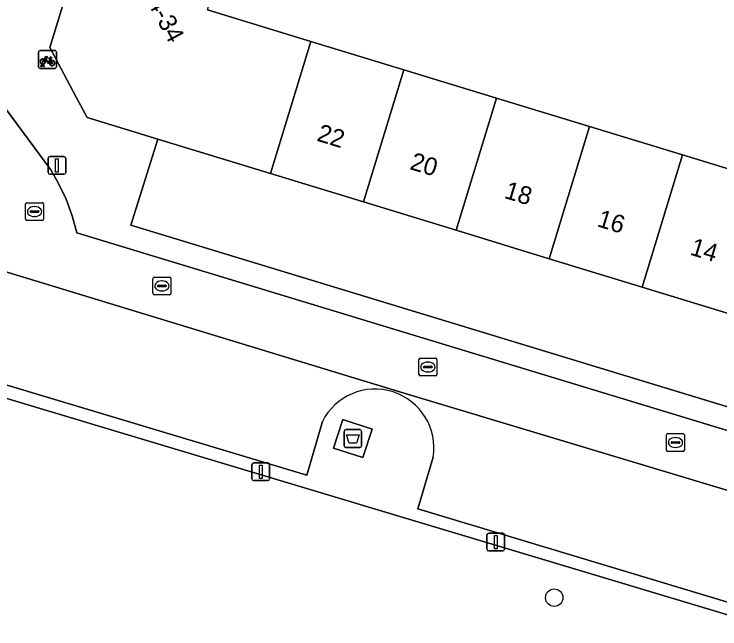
# Model space of a CAD drawing. Extents: x 160304 to 160955, y 383684 to 384161.
# Drawn here: x 160708.64 to 160748.29, y 383760.89 to 383795.43 of the extents above; entities that cross this region are included whole.
import ezdxf

# ---------------------------------------------------------------- set-up
doc = ezdxf.new("R2010")
doc.units = 0
for name, color, linetype in [('IMGEO_Afval_apart_plaats', 7, 'Continuous'), ('IMGEO_Boom', 7, 'Continuous'), ('IMGEO_Brandkraan', 7, 'Continuous'), ('IMGEO_Erf', 7, 'Continuous'), ('IMGEO_Fietsenrek', 7, 'Continuous'), ('IMGEO_Groenvoorziening', 7, 'Continuous'), ('IMGEO_Kolk', 7, 'Continuous'), ('IMGEO_Lichtmast', 7, 'Continuous'), ('IMGEO_Pand', 7, 'Continuous'), ('IMGEO_Pand_nummerreeks', 7, 'Continuous'), ('IMGEO_Parkeervlak_open', 7, 'Continuous'), ('IMGEO_Rijbaan_lokaal_open', 7, 'Continuous'), ('IMGEO_Voetpad_gesloten', 7, 'Continuous'), ('IMGEO_Voetpad_open', 7, 'Continuous')]:
    doc.layers.add(name, color=color, linetype=linetype)

msp = doc.modelspace()

# ---------------------------------------------------------------- linework, layer by layer
at = {"layer": 'IMGEO_Afval_apart_plaats'}
for p, q in [((160727.174, 383771.185), (160727.174, 383771.985)), ((160727.174, 383771.985), (160727.174, 383771.185)), ((160727.274, 383772.085), (160728.064, 383772.085)), ((160728.064, 383772.085), (160727.274, 383772.085)), ((160728.164, 383771.985), (160728.164, 383771.185)), ((160728.164, 383771.185), (160728.164, 383771.985)), ((160728.064, 383771.085), (160727.274, 383771.085)), ((160727.274, 383771.085), (160728.064, 383771.085))]:
    msp.add_line(p, q, dxfattribs=at)
msp.add_lwpolyline([(160727.317, 383771.799), (160728.021, 383771.799), (160727.872, 383771.329), (160727.466, 383771.329), (160727.317, 383771.799)], dxfattribs=at)
for centre, start, end in [((160727.274, 383771.985), 90, 180), ((160727.274, 383771.985), 90, 180), ((160728.064, 383771.985), 0, 90), ((160728.064, 383771.985), 360, 90), ((160727.274, 383771.185), 180, 270), ((160727.274, 383771.185), 180, 270), ((160728.064, 383771.185), 270, 0), ((160728.064, 383771.185), 270, 0)]:
    msp.add_arc(centre, 0.1, start, end, dxfattribs=at)
at = {"layer": 'IMGEO_Boom'}
msp.add_circle((160738.982, 383762.645), 0.489, dxfattribs=at)
at = {"layer": 'IMGEO_Brandkraan'}
for p, q in [((160709.289, 383783.912), (160709.289, 383784.764)), ((160709.364, 383784.838), (160710.216, 383784.838)), ((160709.777, 383784.618), (160709.802, 383784.618)), ((160710.29, 383784.764), (160710.29, 383783.912)), ((160709.548, 383784.332), (160709.548, 383784.344)), ((160709.986, 383784.295), (160709.588, 383784.295)), ((160709.591, 383784.381), (160709.989, 383784.381)), ((160710.032, 383784.344), (160710.032, 383784.332)), ((160710.216, 383783.838), (160709.364, 383783.838)), ((160709.8, 383784.058), (160709.775, 383784.058))]:
    msp.add_line(p, q, dxfattribs=at)
for points in [[(160709.289, 383783.912), (160709.289, 383784.764)], [(160709.364, 383784.838), (160710.216, 383784.838)], [(160710.29, 383784.764), (160710.29, 383783.912)], [(160710.216, 383783.838), (160709.364, 383783.838)]]:
    msp.add_lwpolyline(points, dxfattribs=at)
for centre, radius, start, end in [((160709.366, 383784.762), 0.0765, 91.552, 178.448), ((160709.366, 383784.762), 0.0765, 91.552, 178.448), ((160710.214, 383784.762), 0.0765, 1.552, 88.448), ((160710.214, 383784.762), 0.0765, 1.552, 88.448), ((160709.588, 383784.341), 0.0403, 85.8775, 175.7526), ((160709.585, 383784.331), 0.0366, 178.938, 274.7102), ((160709.989, 383784.338), 0.043, 264.8664, 352.4533), ((160709.993, 383784.343), 0.0386, 1.7309, 96.639), ((160709.366, 383783.914), 0.0765, 181.552, 268.448), ((160709.366, 383783.914), 0.0765, 181.552, 268.448), ((160710.214, 383783.914), 0.0765, 271.552, 358.448), ((160710.214, 383783.914), 0.0765, 271.552, 358.448)]:
    msp.add_arc(centre, radius, start, end, dxfattribs=at)
for centre, major_axis, ratio, start_param, end_param in [((160709.776, 383784.338), (-0.387, 0.002), 0.722429, 4.712389, 7.853982), ((160709.801, 383784.338), (-0.39, 0.002), 0.717154, 1.570796, 4.712389)]:
    msp.add_ellipse(centre, major_axis=major_axis, ratio=ratio, start_param=start_param, end_param=end_param, dxfattribs=at)
at = {"layer": 'IMGEO_Erf'}
msp.add_lwpolyline([(160719.497, 383795.67), (160725.313, 383793.894), (160730.532, 383792.301), (160735.749, 383790.708), (160740.967, 383789.115), (160746.185, 383787.522), (160751.401, 383785.93), (160757.279, 383784.135), (160758.769, 383789.013), (160760.453, 383794.532), (160763.405, 383804.2)], dxfattribs=at)
msp.add_lwpolyline([(160715.206, 383783.583), (160754.942, 383771.483), (160756.398, 383776.288), (160749.136, 383778.505), (160743.919, 383780.098), (160738.701, 383781.692), (160733.483, 383783.285), (160728.266, 383784.878), (160723.048, 383786.471), (160716.717, 383788.404)], close=True, dxfattribs=at)
at = {"layer": 'IMGEO_Fietsenrek'}
for p, q in [((160710.015, 383792.458), (160710.015, 383793.299)), ((160710.015, 383793.299), (160710.015, 383792.458)), ((160710.09, 383793.383), (160710.931, 383793.383)), ((160710.931, 383793.383), (160710.09, 383793.383)), ((160711.015, 383793.308), (160711.015, 383792.467)), ((160711.015, 383792.467), (160711.015, 383793.308)), ((160710.702, 383792.932), (160710.738, 383792.837)), ((160710.142, 383792.467), (160710.181, 383792.627)), ((160710.211, 383792.615), (160710.176, 383792.467)), ((160710.253, 383792.639), (160710.252, 383792.643)), ((160710.294, 383792.467), (160710.26, 383792.609)), ((160710.284, 383792.65), (160710.285, 383792.643)), ((160710.292, 383792.613), (160710.327, 383792.467)), ((160710.94, 383792.383), (160710.099, 383792.383)), ((160710.099, 383792.383), (160710.94, 383792.383)), ((160710.176, 383792.467), (160710.142, 383792.467)), ((160710.327, 383792.467), (160710.294, 383792.467))]:
    msp.add_line(p, q, dxfattribs=at)
for points in [[(160710.328, 383792.909), (160710.423, 383793.073), (160710.509, 383793.059), (160710.511, 383793.05), (160710.455, 383793.039), (160710.428, 383792.994), (160710.684, 383792.953)], [(160710.624, 383792.665), (160710.574, 383792.665), (160710.383, 383792.916), (160710.364, 383792.884)], [(160710.671, 383792.928), (160710.414, 383792.969), (160710.397, 383792.94), (160710.564, 383792.72), (160710.671, 383792.928)], [(160710.719, 383792.83), (160710.689, 383792.907), (160710.58, 383792.689), (160710.623, 383792.689)], [(160710.684, 383792.953), (160710.709, 383793.002), (160710.703, 383793.006), (160710.68, 383793.01), (160710.668, 383793.017), (160710.667, 383793.02), (160710.669, 383793.025), (160710.764, 383793.01), (160710.766, 383793), (160710.756, 383792.987), (160710.744, 383792.981), (160710.73, 383792.987), (160710.702, 383792.932)], [(160710.349, 383792.857), (160710.297, 383792.767), (160710.257, 383792.742), (160710.258, 383792.789), (160710.313, 383792.883)], [(160710.653, 383792.689), (160710.773, 383792.688), (160710.729, 383792.802)], [(160710.749, 383792.809), (160710.804, 383792.664), (160710.654, 383792.664)]]:
    msp.add_lwpolyline(points, dxfattribs=at)
for centre, radius, start, end in [((160710.093, 383793.305), 0.0779, 92.4484, 184.2845), ((160710.093, 383793.305), 0.0779, 92.4484, 184.2845), ((160710.937, 383793.305), 0.0779, 2.4484, 94.2845), ((160710.937, 383793.305), 0.0779, 2.4484, 94.2845), ((160710.255, 383792.768), 0.159, 62.6766, 242.1369), ((160710.255, 383792.768), 0.129, 63.3192, 238.903), ((160710.235, 383792.639), 0.0499, 12.8025, 158.6934), ((160710.255, 383792.768), 0.159, 253.9967, 271.7867), ((160710.235, 383792.639), 0.0174, 12.8025, 163.4502), ((160710.255, 383792.768), 0.129, 253.415, 269.0204), ((160710.255, 383792.768), 0.129, 283.6043, 43.4302), ((160710.255, 383792.768), 0.159, 283.5766, 46.6042), ((160710.782, 383792.684), 0.159, 113.3408, 178.3217), ((160710.782, 383792.684), 0.159, 187.0065, 105.7708), ((160710.782, 383792.684), 0.129, 113.923, 177.9556), ((160710.782, 383792.684), 0.129, 188.6715, 104.5883), ((160710.093, 383792.461), 0.0779, 182.4484, 274.2845), ((160710.093, 383792.461), 0.0779, 182.4484, 274.2845), ((160710.937, 383792.461), 0.0779, 272.4484, 4.2845), ((160710.937, 383792.461), 0.0779, 272.4484, 4.2845)]:
    msp.add_arc(centre, radius, start, end, dxfattribs=at)
at = {"layer": 'IMGEO_Groenvoorziening'}
msp.add_lwpolyline([(160750.716, 383761.085), (160705.399, 383774.681), (160705.031, 383774.791), (160701.01, 383762.556), (160701.624, 383762.297), (160706.457, 383760.242), (160712.957, 383757.775), (160717.807, 383756.023), (160723.606, 383754.258), (160727.379, 383753.098), (160734.157, 383751.25), (160736.004, 383750.747), (160737.653, 383750.355), (160738.57, 383750.307), (160739.205, 383750.36), (160740.079, 383750.61), (160740.894, 383751.087), (160742.228, 383752.015), (160742.866, 383752.503), (160744.775, 383754.285)], close=True, dxfattribs=at)
at = {"layer": 'IMGEO_Kolk'}
for p, q in [((160716.519, 383780.66), (160717.371, 383780.66)), ((160716.444, 383779.734), (160716.444, 383780.586)), ((160716.746, 383780.203), (160717.144, 383780.203)), ((160716.932, 383780.44), (160716.957, 383780.44)), ((160717.445, 383780.586), (160717.445, 383779.734)), ((160716.703, 383780.154), (160716.703, 383780.166)), ((160717.141, 383780.117), (160716.743, 383780.117)), ((160716.955, 383779.88), (160716.93, 383779.88)), ((160717.187, 383780.166), (160717.187, 383780.154)), ((160717.371, 383779.66), (160716.519, 383779.66)), ((160731.384, 383775.179), (160731.384, 383776.031)), ((160731.459, 383776.105), (160732.311, 383776.105)), ((160731.872, 383775.885), (160731.897, 383775.885)), ((160732.385, 383776.031), (160732.385, 383775.179)), ((160731.643, 383775.599), (160731.643, 383775.611)), ((160732.081, 383775.562), (160731.683, 383775.562)), ((160731.686, 383775.648), (160732.084, 383775.648)), ((160732.127, 383775.611), (160732.127, 383775.599)), ((160732.311, 383775.105), (160731.459, 383775.105)), ((160731.895, 383775.325), (160731.87, 383775.325)), ((160745.294, 383770.937), (160745.294, 383771.789)), ((160745.369, 383771.863), (160746.221, 383771.863)), ((160745.782, 383771.643), (160745.807, 383771.643)), ((160746.295, 383771.789), (160746.295, 383770.937)), ((160745.553, 383771.357), (160745.553, 383771.369)), ((160745.991, 383771.32), (160745.593, 383771.32)), ((160745.596, 383771.406), (160745.994, 383771.406)), ((160745.805, 383771.083), (160745.78, 383771.083)), ((160746.037, 383771.369), (160746.037, 383771.357)), ((160746.221, 383770.863), (160745.369, 383770.863))]:
    msp.add_line(p, q, dxfattribs=at)
for points in [[(160716.519, 383780.66), (160717.371, 383780.66)], [(160716.444, 383779.734), (160716.444, 383780.586)], [(160717.445, 383780.586), (160717.445, 383779.734)], [(160717.371, 383779.66), (160716.519, 383779.66)], [(160731.384, 383775.179), (160731.384, 383776.031)], [(160731.459, 383776.105), (160732.311, 383776.105)], [(160732.385, 383776.031), (160732.385, 383775.179)], [(160732.311, 383775.105), (160731.459, 383775.105)], [(160745.294, 383770.937), (160745.294, 383771.789)], [(160745.369, 383771.863), (160746.221, 383771.863)], [(160746.295, 383771.789), (160746.295, 383770.937)], [(160746.221, 383770.863), (160745.369, 383770.863)]]:
    msp.add_lwpolyline(points, dxfattribs=at)
for centre, radius, start, end in [((160716.521, 383780.584), 0.0765, 91.552, 178.448), ((160716.521, 383780.584), 0.0765, 91.552, 178.448), ((160717.369, 383780.584), 0.0765, 1.552, 88.448), ((160717.369, 383780.584), 0.0765, 1.552, 88.448), ((160716.743, 383780.163), 0.0403, 85.8775, 175.7526), ((160717.148, 383780.165), 0.0386, 1.7309, 96.639), ((160716.74, 383780.153), 0.0366, 178.938, 274.7102), ((160717.144, 383780.16), 0.043, 264.8664, 352.4533), ((160716.521, 383779.736), 0.0765, 181.552, 268.448), ((160716.521, 383779.736), 0.0765, 181.552, 268.448), ((160717.369, 383779.736), 0.0765, 271.552, 358.448), ((160717.369, 383779.736), 0.0765, 271.552, 358.448), ((160731.461, 383776.029), 0.0765, 91.552, 178.448), ((160731.461, 383776.029), 0.0765, 91.552, 178.448), ((160732.309, 383776.029), 0.0765, 1.552, 88.448), ((160732.309, 383776.029), 0.0765, 1.552, 88.448), ((160731.683, 383775.608), 0.0403, 85.8775, 175.7526), ((160731.68, 383775.598), 0.0366, 178.938, 274.7102), ((160732.084, 383775.605), 0.043, 264.8664, 352.4533), ((160732.088, 383775.61), 0.0386, 1.7309, 96.639), ((160731.461, 383775.181), 0.0765, 181.552, 268.448), ((160731.461, 383775.181), 0.0765, 181.552, 268.448), ((160732.309, 383775.181), 0.0765, 271.552, 358.448), ((160732.309, 383775.181), 0.0765, 271.552, 358.448), ((160745.371, 383771.787), 0.0765, 91.552, 178.448), ((160745.371, 383771.787), 0.0765, 91.552, 178.448), ((160746.219, 383771.787), 0.0765, 1.552, 88.448), ((160746.219, 383771.787), 0.0765, 1.552, 88.448), ((160745.593, 383771.366), 0.0403, 85.8775, 175.7526), ((160745.59, 383771.356), 0.0366, 178.938, 274.7102), ((160745.994, 383771.363), 0.043, 264.8664, 352.4533), ((160745.998, 383771.368), 0.0386, 1.7309, 96.639), ((160745.371, 383770.939), 0.0765, 181.552, 268.448), ((160745.371, 383770.939), 0.0765, 181.552, 268.448), ((160746.219, 383770.939), 0.0765, 271.552, 358.448), ((160746.219, 383770.939), 0.0765, 271.552, 358.448)]:
    msp.add_arc(centre, radius, start, end, dxfattribs=at)
for centre, major_axis, ratio, start_param, end_param in [((160716.931, 383780.16), (-0.387, 0.002), 0.722429, 4.712389, 7.853982), ((160716.956, 383780.16), (-0.39, 0.002), 0.717154, 1.570796, 4.712389), ((160731.871, 383775.605), (-0.387, 0.002), 0.722429, 4.712389, 7.853982), ((160731.896, 383775.605), (-0.39, 0.002), 0.717154, 1.570796, 4.712389), ((160745.781, 383771.363), (-0.387, 0.002), 0.722429, 4.712389, 7.853982), ((160745.806, 383771.363), (-0.39, 0.002), 0.717154, 1.570796, 4.712389)]:
    msp.add_ellipse(centre, major_axis=major_axis, ratio=ratio, start_param=start_param, end_param=end_param, dxfattribs=at)
at = {"layer": 'IMGEO_Lichtmast'}
for p, q in [((160710.651, 383787.433), (160711.441, 383787.433)), ((160711.441, 383787.433), (160710.651, 383787.433)), ((160710.551, 383786.533), (160710.551, 383787.333)), ((160710.551, 383787.333), (160710.551, 383786.533)), ((160711.541, 383787.333), (160711.541, 383786.533)), ((160711.541, 383786.533), (160711.541, 383787.333)), ((160711.441, 383786.433), (160710.651, 383786.433)), ((160710.651, 383786.433), (160711.441, 383786.433)), ((160722.001, 383769.32), (160722.001, 383770.12)), ((160722.001, 383770.12), (160722.001, 383769.32)), ((160722.101, 383770.22), (160722.891, 383770.22)), ((160722.891, 383770.22), (160722.101, 383770.22)), ((160722.991, 383770.12), (160722.991, 383769.32)), ((160722.991, 383769.32), (160722.991, 383770.12)), ((160722.891, 383769.22), (160722.101, 383769.22)), ((160722.101, 383769.22), (160722.891, 383769.22)), ((160735.205, 383765.371), (160735.205, 383766.171)), ((160735.205, 383766.171), (160735.205, 383765.371)), ((160735.305, 383766.271), (160736.095, 383766.271)), ((160736.095, 383766.271), (160735.305, 383766.271)), ((160736.195, 383766.171), (160736.195, 383765.371)), ((160736.195, 383765.371), (160736.195, 383766.171)), ((160736.095, 383765.271), (160735.305, 383765.271)), ((160735.305, 383765.271), (160736.095, 383765.271))]:
    msp.add_line(p, q, dxfattribs=at)
for points in [[(160710.971, 383787.308), (160711.121, 383787.308), (160711.121, 383786.558), (160710.971, 383786.558), (160710.971, 383787.308)], [(160722.421, 383770.095), (160722.571, 383770.095), (160722.571, 383769.345), (160722.421, 383769.345), (160722.421, 383770.095)], [(160735.625, 383766.146), (160735.775, 383766.146), (160735.775, 383765.396), (160735.625, 383765.396), (160735.625, 383766.146)]]:
    msp.add_lwpolyline(points, dxfattribs=at)
for centre, start, end in [((160710.651, 383787.333), 90, 180), ((160710.651, 383787.333), 90, 180), ((160711.441, 383787.333), 0, 90), ((160711.441, 383787.333), 360, 90), ((160710.651, 383786.533), 180, 270), ((160710.651, 383786.533), 180, 270), ((160711.441, 383786.533), 270, 0), ((160711.441, 383786.533), 270, 0), ((160722.101, 383770.12), 90, 180), ((160722.101, 383770.12), 90, 180), ((160722.891, 383770.12), 0, 90), ((160722.891, 383770.12), 360, 90), ((160722.101, 383769.32), 180, 270), ((160722.101, 383769.32), 180, 270), ((160722.891, 383769.32), 270, 0), ((160722.891, 383769.32), 270, 0), ((160735.305, 383766.171), 90, 180), ((160735.305, 383766.171), 90, 180), ((160736.095, 383766.171), 0, 90), ((160736.095, 383766.171), 360, 90), ((160735.305, 383765.371), 180, 270), ((160735.305, 383765.371), 180, 270), ((160736.095, 383765.371), 270, 0), ((160736.095, 383765.371), 270, 0)]:
    msp.add_arc(centre, 0.1, start, end, dxfattribs=at)
at = {"layer": 'IMGEO_Pand'}
for points in [[(160719.497, 383795.67), (160721.777, 383803.136), (160714.27, 383805.428), (160711.75, 383797.173), (160710.644, 383793.552), (160711.282, 383792.356), (160712.128, 383790.767), (160712.738, 383789.619), (160716.717, 383788.404), (160723.048, 383786.471), (160725.313, 383793.894)], [(160730.532, 383792.301), (160725.313, 383793.894), (160723.048, 383786.471), (160728.266, 383784.878)], [(160735.749, 383790.708), (160730.532, 383792.301), (160728.266, 383784.878), (160733.483, 383783.285)], [(160740.967, 383789.115), (160735.749, 383790.708), (160733.483, 383783.285), (160738.701, 383781.692)], [(160740.967, 383789.115), (160738.701, 383781.692), (160743.919, 383780.098), (160746.185, 383787.522)], [(160746.185, 383787.522), (160743.919, 383780.098), (160749.136, 383778.505), (160751.401, 383785.93)]]:
    msp.add_lwpolyline(points, close=True, dxfattribs=at)
at = {"layer": 'IMGEO_Parkeervlak_open'}
for points in [[(160707.88, 383781.038), (160707.79, 383780.548), (160706.169, 383775.208), (160725.081, 383769.52), (160725.958, 383772.536)], [(160754.197, 383766.989), (160751.924, 383767.711), (160729.983, 383774.308), (160707.88, 383781.038)], [(160732.19, 383770.543), (160731.327, 383767.634), (160750.399, 383761.888), (160751.548, 383765.69)]]:
    msp.add_lwpolyline(points, dxfattribs=at)
msp.add_arc((160728.918, 383771.053), 3.311, 351.147, 153.3843, dxfattribs=at)
at = {"layer": 'IMGEO_Rijbaan_lokaal_open'}
msp.add_lwpolyline([(160707.864, 383781.329), (160707.88, 383781.038), (160729.983, 383774.308), (160751.924, 383767.711), (160752.835, 383770.782), (160712.157, 383783.149), (160711.901, 383784.103), (160711.56, 383785.029), (160711.139, 383785.922), (160710.697, 383786.683), (160707.183, 383791.418)], dxfattribs=at)
at = {"layer": 'IMGEO_Voetpad_gesloten'}
msp.add_lwpolyline([(160727.111, 383772.654), (160726.586, 383771.054), (160728.226, 383770.516), (160728.751, 383772.116)], close=True, dxfattribs=at)
at = {"layer": 'IMGEO_Voetpad_open'}
for points in [[(160703.79, 383797.713), (160703.03, 383795.267), (160703.702, 383794.887), (160704.517, 383794.323), (160705.279, 383793.69), (160705.98, 383792.99), (160706.617, 383792.231), (160707.183, 383791.418), (160710.697, 383786.683), (160711.139, 383785.922), (160711.56, 383785.029), (160711.901, 383784.103), (160712.157, 383783.149), (160752.835, 383770.782)], [(160754.942, 383771.483), (160715.206, 383783.583), (160716.717, 383788.404), (160712.738, 383789.619), (160712.128, 383790.767), (160711.282, 383792.356), (160710.644, 383793.552), (160711.75, 383797.173)], [(160725.958, 383772.536), (160725.081, 383769.52), (160706.169, 383775.208), (160707.79, 383780.548), (160707.88, 383781.038), (160707.25, 383781.231)], [(160707.23, 383780.731), (160705.399, 383774.681), (160750.716, 383761.085), (160752.091, 383765.543), (160751.548, 383765.69), (160750.399, 383761.888), (160731.327, 383767.634), (160732.19, 383770.543)]]:
    msp.add_lwpolyline(points, dxfattribs=at)
msp.add_lwpolyline([(160726.586, 383771.054), (160727.111, 383772.654), (160728.751, 383772.116), (160728.226, 383770.516)], close=True, dxfattribs=at)
msp.add_arc((160728.918, 383771.053), 3.311, 351.147, 153.3843, dxfattribs=at)

# ---------------------------------------------------------------- texts
at = {"layer": 'IMGEO_Pand_nummerreeks'}
for s, rotation, p in [('24-34', 298.0289, (160715.762, 383796.753)), ('22', 343.0231, (160725.599, 383788.327)), ('20', 343.0219, (160730.822, 383786.733)), ('18', 343.0219, (160736.127, 383785.114)), ('16', 343.0219, (160741.342, 383783.522)), ('14', 343.0219, (160746.56, 383781.929))]:
    msp.add_text(s, height=1, rotation=rotation, dxfattribs=at).set_placement(p)

doc.saveas('drawing.dxf')
